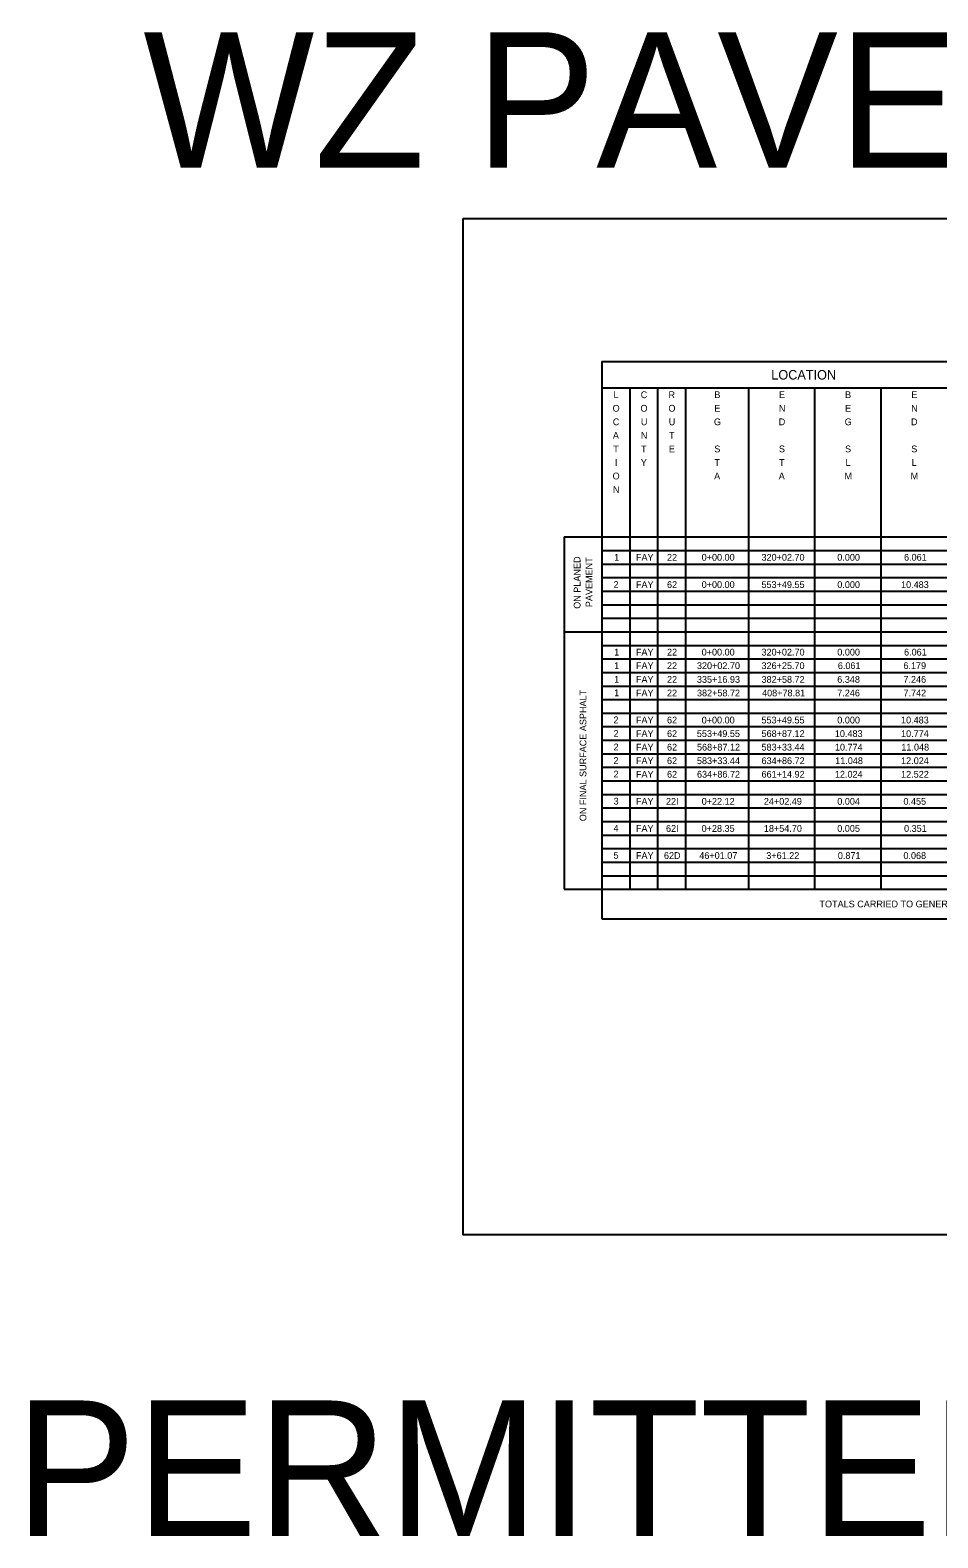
# Model space of a CAD drawing. Extents: x 12522 to 13018, y 1124 to 1902.
# Drawn here: x 12598.47 to 12617.22, y 1640.26 to 1671.42 of the extents above; entities that cross this region are included whole.
import ezdxf

# ---------------------------------------------------------------- set-up
doc = ezdxf.new("R2010")
doc.units = 0
for name, color, linetype in [('SC_Scratch1', 7, 'Continuous'), ('SH_Data', 7, 'Continuous'), ('SH_Text', 7, 'Continuous')]:
    doc.layers.add(name, color=color, linetype=linetype)

msp = doc.modelspace()

# ---------------------------------------------------------------- linework, layer by layer
at = {"layer": 'SC_Scratch1'}
msp.add_lwpolyline([(12607.415, 1667.525), (12637.915, 1667.525), (12637.915, 1646.525), (12607.415, 1646.525)], close=True, dxfattribs=at)
at = {"layer": 'SH_Data'}
for p, q in [((12610.277, 1664.569), (12636.004, 1664.569)), ((12610.277, 1664.569), (12610.277, 1653.056)), ((12610.277, 1664.025), (12636.004, 1664.025)), ((12610.854, 1664.025), (12610.854, 1653.665)), ((12611.43, 1664.025), (12611.43, 1653.665)), ((12612.007, 1664.025), (12612.007, 1653.665)), ((12613.308, 1664.025), (12613.308, 1653.665)), ((12614.675, 1664.025), (12614.675, 1653.665)), ((12616.042, 1664.025), (12616.042, 1653.665)), ((12609.503, 1660.945), (12636.004, 1660.945)), ((12609.503, 1660.945), (12609.503, 1653.665)), ((12610.277, 1660.665), (12636.004, 1660.665)), ((12610.277, 1660.385), (12636.004, 1660.385)), ((12610.277, 1660.105), (12636.004, 1660.105)), ((12610.277, 1659.825), (12636.004, 1659.825)), ((12610.277, 1659.545), (12636.004, 1659.545)), ((12609.503, 1658.985), (12636.004, 1658.985)), ((12610.277, 1659.265), (12636.004, 1659.265)), ((12610.277, 1658.705), (12636.004, 1658.705)), ((12610.277, 1658.425), (12636.004, 1658.425)), ((12610.277, 1658.145), (12636.004, 1658.145)), ((12610.277, 1657.865), (12636.004, 1657.865)), ((12610.277, 1657.585), (12636.004, 1657.585)), ((12610.277, 1657.305), (12636.004, 1657.305)), ((12610.277, 1657.025), (12636.004, 1657.025)), ((12610.277, 1656.745), (12636.004, 1656.745)), ((12610.277, 1656.465), (12636.004, 1656.465)), ((12610.277, 1656.185), (12636.004, 1656.185)), ((12610.277, 1655.905), (12636.004, 1655.905)), ((12610.277, 1655.625), (12636.004, 1655.625)), ((12610.277, 1655.345), (12636.004, 1655.345)), ((12610.277, 1655.065), (12636.004, 1655.065)), ((12610.277, 1654.785), (12636.004, 1654.785)), ((12610.277, 1654.505), (12636.004, 1654.505)), ((12610.277, 1654.225), (12636.004, 1654.225)), ((12610.277, 1653.945), (12636.004, 1653.945)), ((12609.503, 1653.665), (12636.004, 1653.665)), ((12610.277, 1653.056), (12636.004, 1653.056))]:
    msp.add_line(p, q, dxfattribs=at)

# ---------------------------------------------------------------- texts
at = {"layer": 'SC_Scratch1'}
for s, p in [('WZ PAVEMENT MARKING', (12600.805, 1668.578)), ('PERMITTED LANE CLOSURES', (12598.161, 1640.299))]:
    msp.add_text(s, height=2.8, dxfattribs=at).set_placement(p)
at = {"layer": 'SH_Text'}
for s, height, p in [('LOCATION', 0.196, (12613.779, 1664.199)), ('O', 0.14, (12610.501, 1663.535)), ('L', 0.14, (12610.52, 1663.815)), ('O', 0.14, (12611.077, 1663.535)), ('C', 0.14, (12611.082, 1663.815)), ('O', 0.14, (12611.654, 1663.535)), ('R', 0.14, (12611.656, 1663.815)), ('B', 0.14, (12612.603, 1663.815)), ('E', 0.14, (12612.603, 1663.535)), ('N', 0.14, (12613.935, 1663.535)), ('E', 0.14, (12613.937, 1663.815)), ('B', 0.14, (12615.304, 1663.815)), ('E', 0.14, (12615.304, 1663.535)), ('N', 0.14, (12616.669, 1663.535)), ('E', 0.14, (12616.672, 1663.815)), ('C', 0.14, (12610.505, 1663.255)), ('U', 0.14, (12611.086, 1663.255)), ('U', 0.14, (12611.662, 1663.255)), ('G', 0.14, (12612.594, 1663.255)), ('D', 0.14, (12613.933, 1663.255)), ('G', 0.14, (12615.296, 1663.255)), ('D', 0.14, (12616.667, 1663.255)), ('A', 0.14, (12610.507, 1662.975)), ('N', 0.14, (12611.086, 1662.975)), ('T', 0.14, (12611.666, 1662.975)), ('T', 0.14, (12610.514, 1662.695)), ('T', 0.14, (12611.09, 1662.695)), ('E', 0.14, (12611.664, 1662.695)), ('S', 0.14, (12612.603, 1662.695)), ('S', 0.14, (12613.937, 1662.695)), ('S', 0.14, (12615.304, 1662.695)), ('S', 0.14, (12616.671, 1662.695)), ('I', 0.14, (12610.549, 1662.415)), ('Y', 0.14, (12611.084, 1662.415)), ('T', 0.14, (12612.605, 1662.415)), ('T', 0.14, (12613.939, 1662.415)), ('L', 0.14, (12615.313, 1662.415)), ('L', 0.14, (12616.68, 1662.415)), ('O', 0.14, (12610.501, 1662.135)), ('A', 0.14, (12612.598, 1662.135)), ('A', 0.14, (12613.933, 1662.135)), ('M', 0.14, (12615.292, 1662.135)), ('M', 0.14, (12616.659, 1662.135)), ('N', 0.14, (12610.509, 1661.855)), ('1', 0.14, (12610.533, 1660.455)), ('FAY', 0.14, (12610.983, 1660.455)), ('22', 0.14, (12611.625, 1660.455)), ('0+00.00', 0.14, (12612.341, 1660.455)), ('320+02.70', 0.14, (12613.577, 1660.455)), ('0.000', 0.14, (12615.143, 1660.455)), ('6.061', 0.14, (12616.522, 1660.455)), ('2', 0.14, (12610.521, 1659.895)), ('FAY', 0.14, (12610.983, 1659.891)), ('62', 0.14, (12611.625, 1659.891)), ('0+00.00', 0.14, (12612.341, 1659.891)), ('553+49.55', 0.14, (12613.577, 1659.891)), ('0.000', 0.14, (12615.143, 1659.891)), ('10.483', 0.14, (12616.46, 1659.891)), ('1', 0.14, (12610.533, 1658.495)), ('1', 0.14, (12610.533, 1658.215)), ('FAY', 0.14, (12610.983, 1658.495)), ('FAY', 0.14, (12610.983, 1658.215)), ('22', 0.14, (12611.625, 1658.495)), ('22', 0.14, (12611.625, 1658.215)), ('320+02.70', 0.14, (12612.243, 1658.215)), ('0+00.00', 0.14, (12612.341, 1658.495)), ('320+02.70', 0.14, (12613.577, 1658.495)), ('326+25.70', 0.14, (12613.577, 1658.215)), ('0.000', 0.14, (12615.143, 1658.495)), ('6.061', 0.14, (12615.154, 1658.215)), ('6.179', 0.14, (12616.509, 1658.215)), ('6.061', 0.14, (12616.522, 1658.495)), ('1', 0.14, (12610.533, 1657.935)), ('FAY', 0.14, (12610.983, 1657.931)), ('22', 0.14, (12611.625, 1657.931)), ('335+16.93', 0.14, (12612.243, 1657.931)), ('382+58.72', 0.14, (12613.578, 1657.931)), ('6.348', 0.14, (12615.142, 1657.931)), ('7.246', 0.14, (12616.509, 1657.931)), ('1', 0.14, (12610.533, 1657.655)), ('FAY', 0.14, (12610.983, 1657.651)), ('22', 0.14, (12611.625, 1657.651)), ('382+58.72', 0.14, (12612.244, 1657.651)), ('408+78.81', 0.14, (12613.589, 1657.651)), ('7.246', 0.14, (12615.142, 1657.651)), ('7.742', 0.14, (12616.51, 1657.651)), ('2', 0.14, (12610.521, 1657.095)), ('FAY', 0.14, (12610.983, 1657.091)), ('62', 0.14, (12611.625, 1657.091)), ('0+00.00', 0.14, (12612.341, 1657.091)), ('553+49.55', 0.14, (12613.577, 1657.091)), ('0.000', 0.14, (12615.143, 1657.091)), ('10.483', 0.14, (12616.46, 1657.091)), ('2', 0.14, (12610.521, 1656.815)), ('FAY', 0.14, (12610.983, 1656.811)), ('62', 0.14, (12611.625, 1656.811)), ('553+49.55', 0.14, (12612.242, 1656.811)), ('568+87.12', 0.14, (12613.578, 1656.811)), ('10.483', 0.14, (12615.093, 1656.811)), ('10.774', 0.14, (12616.461, 1656.811)), ('2', 0.14, (12610.521, 1656.535)), ('FAY', 0.14, (12610.983, 1656.531)), ('62', 0.14, (12611.625, 1656.531)), ('568+87.12', 0.14, (12612.244, 1656.531)), ('583+33.44', 0.14, (12613.577, 1656.531)), ('10.774', 0.14, (12615.094, 1656.531)), ('11.048', 0.14, (12616.467, 1656.531)), ('2', 0.14, (12610.521, 1656.255)), ('FAY', 0.14, (12610.983, 1656.251)), ('62', 0.14, (12611.625, 1656.251)), ('583+33.44', 0.14, (12612.243, 1656.251)), ('634+86.72', 0.14, (12613.578, 1656.251)), ('11.048', 0.14, (12615.1, 1656.251)), ('12.024', 0.14, (12616.461, 1656.251)), ('2', 0.14, (12610.521, 1655.975)), ('FAY', 0.14, (12610.983, 1655.971)), ('62', 0.14, (12611.625, 1655.971)), ('634+86.72', 0.14, (12612.244, 1655.971)), ('661+14.92', 0.14, (12613.578, 1655.971)), ('12.024', 0.14, (12615.094, 1655.971)), ('12.522', 0.14, (12616.461, 1655.971)), ('3', 0.14, (12610.521, 1655.415)), ('FAY', 0.14, (12610.983, 1655.411)), ('22I', 0.14, (12611.604, 1655.411)), ('0+22.12', 0.14, (12612.341, 1655.411)), ('24+02.49', 0.14, (12613.626, 1655.411)), ('0.004', 0.14, (12615.143, 1655.411)), ('0.455', 0.14, (12616.509, 1655.411)), ('4', 0.14, (12610.521, 1654.855)), ('FAY', 0.14, (12610.983, 1654.851)), ('62I', 0.14, (12611.604, 1654.851)), ('0+28.35', 0.14, (12612.34, 1654.851)), ('18+54.70', 0.14, (12613.626, 1654.851)), ('0.005', 0.14, (12615.142, 1654.851)), ('0.351', 0.14, (12616.522, 1654.851)), ('5', 0.14, (12610.52, 1654.295)), ('FAY', 0.14, (12610.983, 1654.291)), ('62D', 0.14, (12611.562, 1654.291)), ('46+01.07', 0.14, (12612.292, 1654.291)), ('3+61.22', 0.14, (12613.676, 1654.291)), ('0.871', 0.14, (12615.154, 1654.291)), ('0.068', 0.14, (12616.509, 1654.291)), ('TOTALS CARRIED TO GENERAL SUMMARY', 0.14, (12614.775, 1653.29))]:
    msp.add_text(s, height=height, dxfattribs=at).set_placement(p)
for s, p in [('ON PLANED ', (12609.838, 1659.461)), ('PAVEMENT', (12610.083, 1659.496)), ('ON FINAL SURFACE ASPHALT', (12609.96, 1655.07))]:
    msp.add_text(s, height=0.14, rotation=90, dxfattribs=at).set_placement(p)

doc.saveas('drawing.dxf')
